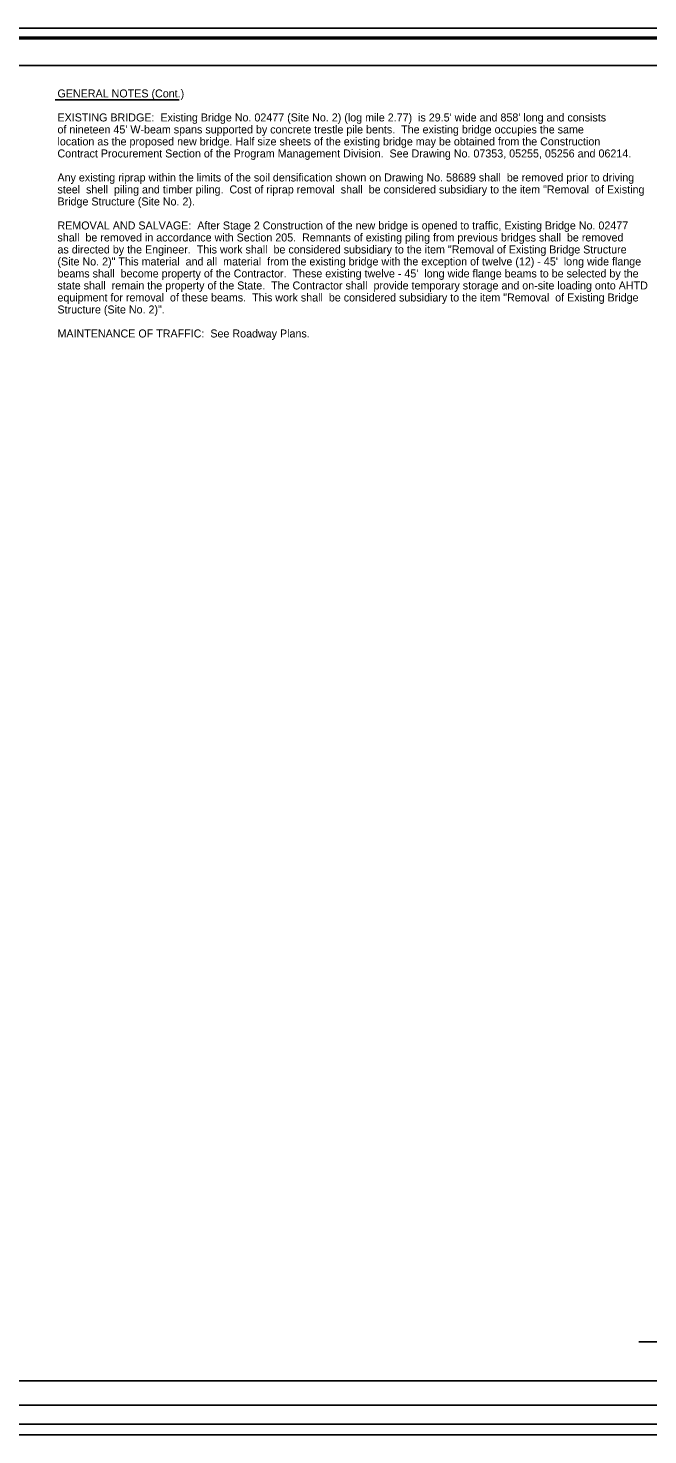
# Model space of a CAD drawing. Extents: x -290 to 969, y 225 to 885.
# Drawn here: x 162 to 452, y 225 to 885 of the extents above; entities that cross this region are included whole.
import ezdxf

# ---------------------------------------------------------------- set-up
doc = ezdxf.new("R2010")
doc.units = 0
for name, color, linetype in [('B_Border', 7, 'Continuous'), ('B_Layout_Work', 7, 'Continuous'), ('border', 7, 'Continuous'), ('Border 2660-Hwy18 - Level 62', 7, 'Continuous'), ('Border 2660-Hwy18 - Level 63', 7, 'Continuous'), ('Level 62 PDF', 7, 'Continuous')]:
    doc.layers.add(name, color=color, linetype=linetype)

msp = doc.modelspace()

# ---------------------------------------------------------------- linework, layer by layer
at = {"layer": 'B_Layout_Work'}
msp.add_line((174.23, 851.04), (232.32, 851.04), dxfattribs=at)
at = {"layer": 'border'}
for p, q in [((-238.51, 867.08), (721.82, 867.08)), ((447.65, 268.97), (511.91, 268.97)), ((721.82, 250.72), (-238.51, 250.72))]:
    msp.add_line(p, q, dxfattribs=at)
at = {"layer": 'Border 2660-Hwy18 - Level 62'}
msp.add_lwpolyline([(-287.11, 884.65), (736.44, 884.65), (736.44, 230.36), (-287.11, 230.36)], close=True, dxfattribs=at)
at = {"layer": 'Border 2660-Hwy18 - Level 63'}
msp.add_lwpolyline([(-290.45, 880.36), (729.54, 880.36), (729.54, 239.27), (-290.45, 239.27)], close=True, dxfattribs=at)
at = {"layer": 'Level 62 PDF'}
msp.add_lwpolyline([(-279.61, 879.65), (743.94, 879.65), (743.94, 225.36), (-279.61, 225.36)], close=True, dxfattribs=at)

# ---------------------------------------------------------------- texts
at = {"layer": 'B_Border'}
for s, p in [('GENERAL NOTES (Cont.)', (175.37, 852.17)), ("EXISTING BRIDGE:  Existing Bridge No. 02477 (Site No. 2) (log mile 2.77)  is 29.5' wide and 858' long and consists", (175.37, 840.92)), ("of nineteen 45' W-beam spans supported by concrete trestle pile bents.  The existing bridge occupies the same", (175.37, 835.29)), ('location as the proposed new bridge. Half size sheets of the existing bridge may be obtained from the Construction', (175.37, 829.67)), ('Contract Procurement Section of the Program Management Division.  See Drawing No. 07353, 05255, 05256 and 06214.', (175.37, 824.04)), ('Any existing riprap within the limits of the soil densification shown on Drawing No. 58689 shall  be removed prior to driving', (175.37, 812.79)), ('steel  shell  piling and timber piling.  Cost of riprap removal  shall  be considered subsidiary to the item "Removal  of Existing', (175.37, 807.17)), ('Bridge Structure (Site No. 2).', (175.37, 801.54)), ('REMOVAL AND SALVAGE:  After Stage 2 Construction of the new bridge is opened to traffic, Existing Bridge No. 02477', (175.37, 790.29)), ('shall  be removed in accordance with Section 205.  Remnants of existing piling from previous bridges shall  be removed', (175.37, 784.67)), ('as directed by the Engineer.  This work shall  be considered subsidiary to the item "Removal of Existing Bridge Structure', (175.37, 779.04)), ('(Site No. 2)" This material  and all  material  from the existing bridge with the exception of twelve (12) - 45\'  long wide flange', (175.37, 773.42)), ("beams shall  become property of the Contractor.  These existing twelve - 45'  long wide flange beams to be selected by the", (175.37, 767.79)), ('state shall  remain the property of the State.  The Contractor shall  provide temporary storage and on-site loading onto AHTD', (175.37, 762.17)), ('equipment for removal  of these beams.  This work shall  be considered subsidiary to the item "Removal  of Existing Bridge', (175.37, 756.54)), ('Structure (Site No. 2)".', (175.37, 750.92)), ('MAINTENANCE OF TRAFFIC:  See Roadway Plans.', (175.37, 739.67))]:
    msp.add_text(s, height=3.75, dxfattribs=at).set_placement(p)

doc.saveas('drawing.dxf')
